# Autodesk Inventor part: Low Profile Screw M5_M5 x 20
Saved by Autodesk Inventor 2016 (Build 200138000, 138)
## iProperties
Created: 2016-01
Part Number: Low Profile Screw M5_M5 x 20
Material: Generic
Document SubType Name: Modeling
Designer: John
Density: 1 g/cm^3
Appearance: Default
Author: John
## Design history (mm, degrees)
feature "CUT-EXTRUDE2"
body "Solid1"
